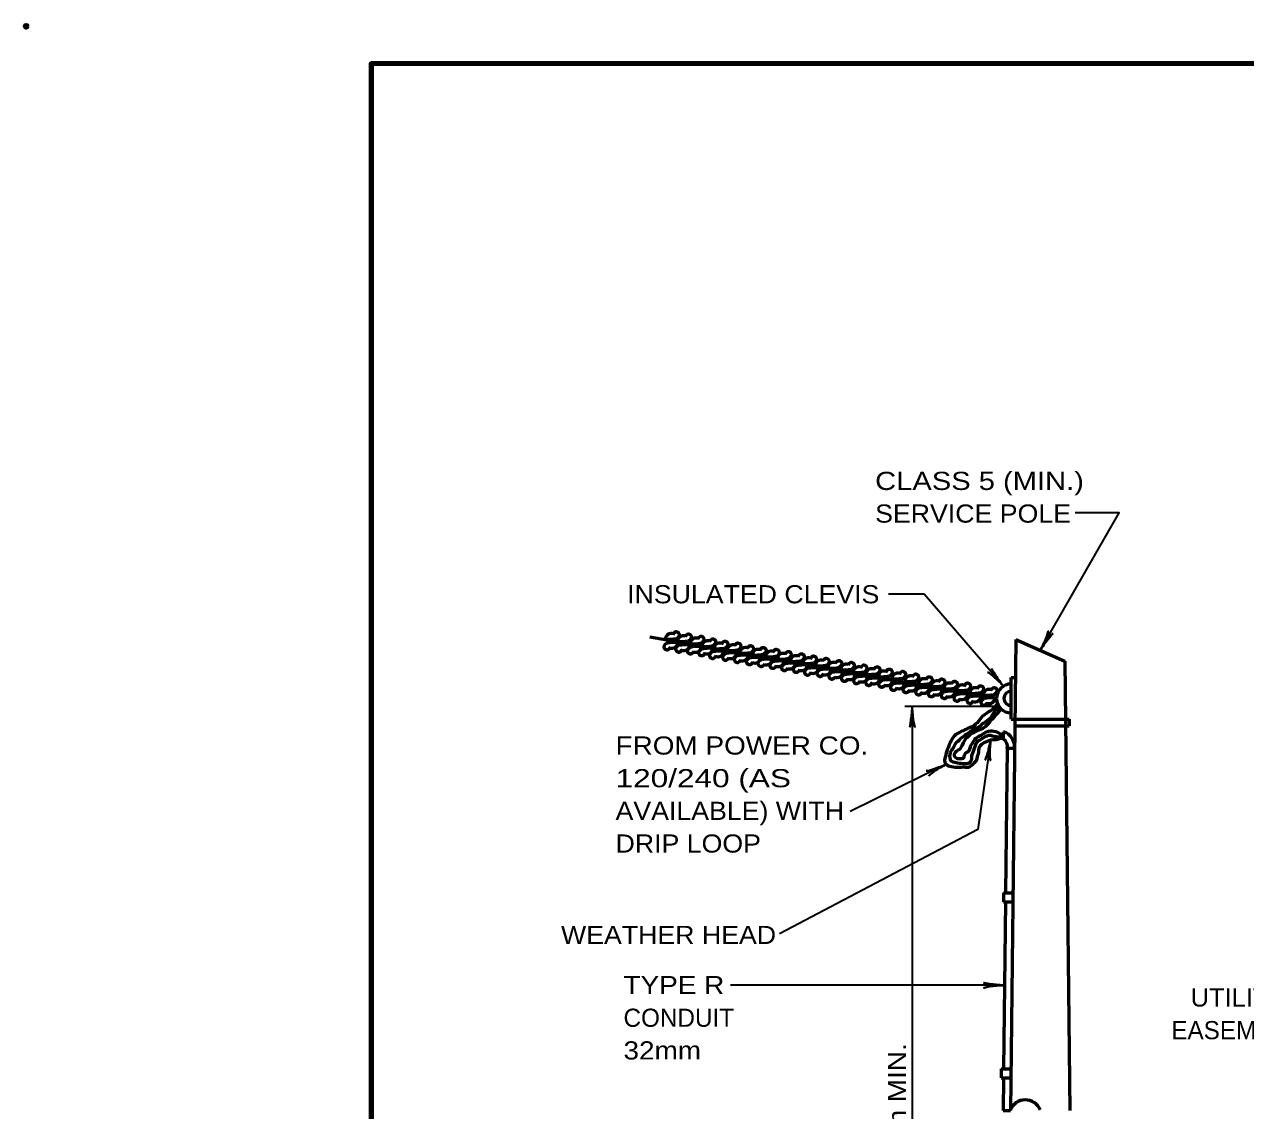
# Model space of a CAD drawing. Extents: x -111 to 744, y -77 to 467.
# Drawn here: x -111.3 to 90.6, y 287.1 to 466.7 of the extents above; entities that cross this region are included whole.
import ezdxf
from ezdxf.enums import TextEntityAlignment as Align

# ---------------------------------------------------------------- set-up
doc = ezdxf.new("R2010")
doc.units = 0
doc.header["$LTSCALE"] = 1.2
doc.header["$PDMODE"] = 32
doc.header["$PDSIZE"] = 0.6
doc.layers.add('1', color=7, linetype='Continuous', lineweight=53)

msp = doc.modelspace()

# ---------------------------------------------------------------- linework, layer by layer
at = {"layer": '1', "lineweight": 35}
for p, q in [((37.467, 372.463), (31.541, 372.476)), ((50.549, 357.271), (37.467, 372.463)), ((49.884, 353.927), (34.284, 353.927)), ((41.118, 344.372), (25.249, 336.554)), ((50.739, 307.831), (5.456, 307.865))]:
    msp.add_line(p, q, dxfattribs=at)
at = {"layer": '1'}
for p, q in [((49.439, 355.247), (-7.877, 365.353)), ((52.589, 364.996), (51.704, 287.117)), ((52.589, 364.996), (60.705, 361.396)), ((60.705, 361.396), (61.549, 287.117)), ((51.839, 358.697), (52.517, 358.697)), ((51.839, 351.797), (51.839, 358.697)), ((51.839, 351.797), (61.427, 351.797)), ((61.427, 351.797), (61.427, 350.717)), ((50.585, 348.511), (50.585, 349.711)), ((52.427, 350.717), (61.427, 350.717)), ((51.185, 347.011), (50.913, 323.131)), ((51.185, 347.011), (52.385, 347.011)), ((50.596, 323.131), (52.096, 323.131)), ((50.596, 323.131), (50.596, 321.631)), ((50.896, 321.631), (50.583, 294.031)), ((50.596, 321.631), (52.096, 321.631)), ((50.204, 294.031), (51.704, 294.031)), ((50.204, 294.031), (50.204, 292.531)), ((50.204, 292.531), (51.704, 292.531)), ((50.565, 292.531), (50.504, 287.131)), ((50.504, 287.131), (51.704, 287.131))]:
    msp.add_line(p, q, dxfattribs=at)
at = {"layer": '1', "lineweight": 158}
msp.add_lwpolyline([(737.728, 460.265), (-53.972, 460.165), (-53.872, -65.835)], dxfattribs=at)
at = {"layer": '1', "lineweight": 35}
for points in [[(56.647, 363.196), (69.692, 385.907), (62.415, 385.907)], [(35.483, 353.927), (35.483, 211.531), (35.483, 139.517)], [(48.457, 348.411), (46.345, 333.592), (13.529, 316.314)]]:
    msp.add_lwpolyline(points, dxfattribs=at)
at = {"layer": '1'}
for points in [[(49.666, 354.362), (49.472, 354.169), (49.327, 354.024), (49.158, 353.83), (48.965, 353.636), (48.82, 353.491), (48.578, 353.322), (48.384, 353.128), (48.118, 353.007), (47.804, 352.79), (47.465, 352.596), (47.272, 352.403), (47.054, 352.233), (46.812, 351.992), (46.692, 351.822), (46.474, 351.532), (46.232, 351.217), (45.966, 350.976), (45.724, 350.782), (45.434, 350.613), (45.241, 350.516), (45.023, 350.443), (44.805, 350.347), (44.612, 350.25), (44.394, 350.129), (44.177, 350.032), (43.935, 349.911), (43.669, 349.814), (43.427, 349.694), (43.185, 349.572), (42.968, 349.452), (42.677, 349.258), (42.436, 349.016), (42.194, 348.75), (42.024, 348.484), (41.855, 348.194), (41.734, 347.904), (41.613, 347.637), (41.541, 347.396), (41.444, 347.105), (41.275, 346.791), (41.178, 346.549), (41.105, 346.259), (41.033, 345.944), (40.96, 345.654), (40.888, 345.339), (40.84, 345.049), (40.864, 344.662), (40.985, 344.493), (41.251, 344.251), (41.444, 344.13), (41.71, 344.057), (41.952, 343.985), (42.315, 343.936), (42.556, 343.912), (42.871, 343.888), (43.137, 343.888), (43.403, 343.912), (43.645, 343.912), (43.911, 343.936), (44.225, 343.888), (44.588, 343.864), (44.805, 343.888), (45.071, 344.009), (45.337, 344.202), (45.555, 344.372), (45.724, 344.59), (45.942, 344.807), (46.111, 345.001), (46.208, 345.291), (46.28, 345.581), (46.353, 345.872), (46.45, 346.089), (46.498, 346.404), (46.522, 346.718), (46.546, 347.033), (46.643, 347.274), (46.788, 347.492), (47.006, 347.686), (47.199, 347.879), (47.417, 347.976), (47.635, 348.073), (47.925, 348.17), (48.215, 348.315), (48.457, 348.411), (48.844, 348.484), (49.086, 348.46), (49.352, 348.484), (49.642, 348.532), (49.932, 348.605), (50.174, 348.653), (50.44, 348.678), (50.536, 348.702)], [(49.884, 353.927), (49.448, 353.516), (49.279, 353.346), (49.013, 352.959), (48.82, 352.669), (48.674, 352.475), (48.529, 352.113), (48.312, 351.919), (48.07, 351.75), (47.828, 351.556), (47.562, 351.338), (47.296, 351.169), (47.03, 351.024), (46.812, 350.758), (46.619, 350.613), (46.208, 350.395), (45.869, 350.274), (45.628, 350.153), (45.434, 350.008), (45.216, 349.887), (44.999, 349.742), (44.757, 349.524), (44.588, 349.403), (44.37, 349.258), (44.152, 349.089), (43.79, 348.871), (43.62, 348.75), (43.475, 348.605), (43.258, 348.363), (43.04, 348.145), (42.822, 348), (42.653, 347.807), (42.532, 347.589), (42.411, 347.347), (42.315, 347.129), (42.169, 346.887), (42, 346.718), (41.855, 346.476), (41.783, 346.234), (41.71, 345.993), (41.662, 345.726), (41.686, 345.46), (41.758, 345.17), (41.879, 344.928), (42.194, 344.759), (42.532, 344.686), (42.968, 344.614), (43.282, 344.565), (43.524, 344.541), (43.886, 344.517), (44.128, 344.517), (44.418, 344.517), (44.709, 344.541), (44.95, 344.59), (45.12, 344.759), (45.192, 344.952), (45.313, 345.218), (45.337, 345.509), (45.361, 345.726), (45.41, 345.968), (45.482, 346.234), (45.603, 346.525), (45.748, 346.839), (45.845, 347.178), (45.942, 347.492), (46.039, 347.783), (46.184, 348.024), (46.377, 348.218), (46.595, 348.363), (46.861, 348.532), (47.151, 348.702), (47.393, 348.847), (47.659, 348.992), (47.876, 349.065), (48.167, 349.161), (48.408, 349.161), (48.723, 349.089), (49.037, 349.016), (49.4, 348.968), (49.666, 348.919), (49.932, 348.944), (50.198, 348.992), (50.416, 349.065), (50.609, 349.113)], [(50.198, 353.491), (49.932, 353.177), (49.472, 352.717), (49.255, 352.5), (49.086, 352.282), (48.771, 351.871), (48.626, 351.725), (48.481, 351.58), (48.239, 351.314), (47.973, 350.976), (47.804, 350.806), (47.61, 350.589), (47.393, 350.419), (47.151, 350.274), (46.764, 350.105), (46.522, 350.008), (46.305, 349.911), (46.111, 349.814), (45.845, 349.694), (45.482, 349.5), (45.144, 349.307), (44.975, 349.161), (44.781, 348.992), (44.539, 348.798), (44.273, 348.581), (44.104, 348.266), (43.911, 347.928), (43.693, 347.396), (43.572, 347.226), (43.354, 346.887), (43.04, 346.67), (42.726, 346.452), (42.556, 346.283), (42.411, 346.017), (42.436, 345.775), (42.605, 345.557), (42.895, 345.339), (43.233, 345.291), (43.451, 345.291), (43.717, 345.291), (43.935, 345.388), (44.056, 345.63), (44.152, 345.847), (44.249, 346.065), (44.37, 346.234), (44.588, 346.38), (44.878, 346.621), (45.023, 346.936), (45.12, 347.226), (45.192, 347.468), (45.337, 347.686), (45.458, 347.879), (45.579, 348.073), (45.7, 348.291), (45.845, 348.532), (46.014, 348.702), (46.256, 348.871), (46.498, 349.016), (46.861, 349.161), (47.127, 349.331), (47.32, 349.476), (47.538, 349.621), (47.731, 349.742), (48.094, 349.863), (48.408, 349.911), (48.699, 349.887), (48.965, 349.863), (49.327, 349.766), (49.545, 349.669), (49.763, 349.548), (50.004, 349.403), (50.198, 349.307), (50.488, 349.185), (50.585, 349.161)]]:
    msp.add_lwpolyline(points, dxfattribs=at)
for centre, radius, start, end in [((51.839, 355.247), 2.4, 90, 270), ((51.839, 355.247), 1.2, 90, 270), ((49.865, 347.281), 2.534, 353.86968, 73.51046), ((49.936, 347.381), 1.302, 343.45685, 60.14597), ((54.165, 286.251), 2.644, 21.451, 158.54901)]:
    msp.add_arc(centre, radius, start, end, dxfattribs=at)
at = {"layer": '1', "lineweight": 40}
for centre, major_axis, ratio, start_param, end_param in [((57.012, 364.497), (-0.905, -1.951), 0.122415, 0.8963533, 3.1415927), ((57.012, 364.497), (-0.905, -1.951), 0.122415, 0.8963533, 3.1415927), ((57.537, 364.236), (1.233, 1.723), 0.07063, 6.2823074, 8.5597026), ((57.537, 364.236), (1.233, 1.723), 0.07063, 6.2823074, 8.5597026), ((49.444, 358.047), (1.54, -1.502), 0.122415, 0.8963533, 3.1415927), ((49.444, 358.047), (1.54, -1.502), 0.122415, 0.8963533, 3.1415927), ((49.864, 358.455), (1.216, -1.735), 0.07063, 3.1407148, 5.41811), ((49.864, 358.455), (1.216, -1.735), 0.07063, 3.1407148, 5.41811), ((35.23, 352.582), (0.211, 2.108), 0.07063, 3.1407148, 5.41811), ((35.23, 352.582), (0.211, 2.108), 0.07063, 3.1407148, 5.41811), ((35.23, 352.582), (0.211, 2.108), 0.07063, 3.1407148, 5.41811), ((35.815, 352.617), (-0.187, 2.143), 0.122415, 0.8963533, 3.1415927), ((35.815, 352.617), (-0.187, 2.143), 0.122415, 0.8963533, 3.1415927), ((35.815, 352.617), (-0.187, 2.143), 0.122415, 0.8963533, 3.1415927), ((48.016, 347.116), (-0.506, -2.057), 0.07063, 6.2823074, 8.5597026), ((48.016, 347.116), (-0.506, -2.057), 0.07063, 6.2823074, 8.5597026), ((48.6, 347.068), (0.117, 2.148), 0.122415, 0.8963533, 3.1415927), ((48.6, 347.068), (0.117, 2.148), 0.122415, 0.8963533, 3.1415927), ((39.799, 344.005), (-1.984, -0.742), 0.07063, 6.2823074, 8.5597026), ((39.799, 344.005), (-1.984, -0.742), 0.07063, 6.2823074, 8.5597026), ((40.09, 343.496), (1.839, 1.115), 0.122415, 0.8963533, 3.1415927), ((40.09, 343.496), (1.839, 1.115), 0.122415, 0.8963533, 3.1415927), ((49.43, 307.5), (2.143, 0.186), 0.122415, 0.8963533, 3.1415927), ((49.395, 308.085), (-2.108, 0.212), 0.07063, 6.2823074, 8.5597026)]:
    msp.add_ellipse(centre, major_axis=major_axis, ratio=ratio, start_param=start_param, end_param=end_param, dxfattribs=at)
at = {"layer": '1'}
for points in [[(-4.053, 365.839), (-3.532, 366.286), (-3.086, 365.988), (-3.383, 365.169), (-3.979, 365.02), (-5.244, 365.169), (-4.797, 365.913), (-4.053, 365.988)], [(-2.044, 365.467), (-1.523, 365.913), (-1.076, 365.616), (-1.374, 364.797), (-1.969, 364.648), (-3.234, 364.797), (-2.788, 365.541), (-2.044, 365.616)], [(0.04, 365.095), (0.561, 365.541), (1.007, 365.243), (0.71, 364.425), (0.114, 364.276), (-1.151, 364.425), (-0.704, 365.169), (0.04, 365.243)], [(-4.499, 363.68), (-5.02, 363.233), (-5.467, 363.531), (-5.169, 364.35), (-4.574, 364.499), (-3.309, 364.35), (-3.755, 363.606), (-4.499, 363.531)], [(-2.564, 363.308), (-3.085, 362.861), (-3.532, 363.159), (-3.234, 363.978), (-2.639, 364.127), (-1.374, 363.978), (-1.82, 363.233), (-2.564, 363.159)], [(-0.63, 363.01), (-1.151, 362.564), (-1.597, 362.861), (-1.299, 363.68), (-0.704, 363.829), (0.561, 363.68), (0.115, 362.936), (-0.63, 362.861)], [(1.231, 362.712), (0.71, 362.266), (0.264, 362.564), (0.561, 363.382), (1.157, 363.531), (2.421, 363.382), (1.975, 362.638), (1.231, 362.564)], [(1.975, 364.648), (2.496, 365.095), (2.942, 364.797), (2.645, 363.978), (2.049, 363.829), (0.784, 363.978), (1.231, 364.722), (1.975, 364.797)], [(3.984, 364.276), (4.505, 364.722), (4.952, 364.425), (4.654, 363.606), (4.059, 363.457), (2.794, 363.606), (3.24, 364.35), (3.984, 364.425)], [(6.142, 363.978), (6.663, 364.425), (7.11, 364.127), (6.812, 363.308), (6.217, 363.159), (4.952, 363.308), (5.398, 364.052), (6.142, 364.127)], [(8.226, 363.531), (8.747, 363.978), (9.193, 363.68), (8.896, 362.861), (8.3, 362.712), (7.035, 362.861), (7.482, 363.606), (8.226, 363.68)], [(10.309, 363.233), (10.83, 363.68), (11.277, 363.382), (10.979, 362.564), (10.384, 362.415), (9.119, 362.564), (9.565, 363.308), (10.309, 363.382)], [(12.468, 362.936), (12.989, 363.382), (13.435, 363.085), (13.137, 362.266), (12.542, 362.117), (11.277, 362.266), (11.724, 363.01), (12.468, 363.085)], [(3.017, 362.266), (2.496, 361.819), (2.05, 362.117), (2.347, 362.936), (2.943, 363.085), (4.208, 362.936), (3.761, 362.191), (3.017, 362.117)], [(5.175, 361.968), (4.654, 361.521), (4.208, 361.819), (4.505, 362.638), (5.101, 362.787), (6.365, 362.638), (5.919, 361.894), (5.175, 361.819)], [(7.11, 361.596), (6.589, 361.149), (6.142, 361.447), (6.44, 362.266), (7.035, 362.415), (8.3, 362.266), (7.854, 361.521), (7.11, 361.447)], [(9.119, 361.224), (8.598, 360.777), (8.152, 361.075), (8.449, 361.894), (9.045, 362.042), (10.31, 361.894), (9.863, 361.149), (9.119, 361.075)], [(11.054, 360.926), (10.533, 360.479), (10.086, 360.777), (10.384, 361.596), (10.979, 361.745), (12.244, 361.596), (11.798, 360.851), (11.054, 360.777)], [(12.989, 360.628), (12.468, 360.181), (12.021, 360.479), (12.319, 361.298), (12.914, 361.447), (14.179, 361.298), (13.733, 360.554), (12.989, 360.479)], [(14.477, 362.564), (14.998, 363.01), (15.444, 362.712), (15.147, 361.894), (14.551, 361.745), (13.286, 361.894), (13.733, 362.638), (14.477, 362.712)], [(16.635, 362.191), (17.156, 362.638), (17.602, 362.34), (17.305, 361.521), (16.709, 361.372), (15.444, 361.521), (15.891, 362.266), (16.635, 362.34)], [(18.644, 361.819), (19.165, 362.266), (19.611, 361.968), (19.314, 361.149), (18.719, 361), (17.454, 361.149), (17.9, 361.894), (18.644, 361.968)], [(20.728, 361.447), (21.249, 361.894), (21.695, 361.596), (21.398, 360.777), (20.802, 360.628), (19.537, 360.777), (19.984, 361.521), (20.728, 361.596)], [(22.812, 361.075), (23.332, 361.521), (23.779, 361.224), (23.481, 360.405), (22.886, 360.256), (21.621, 360.405), (22.067, 361.149), (22.812, 361.224)], [(14.924, 360.256), (14.403, 359.809), (13.956, 360.107), (14.254, 360.926), (14.849, 361.075), (16.114, 360.926), (15.668, 360.181), (14.924, 360.107)], [(16.858, 359.958), (16.337, 359.512), (15.891, 359.809), (16.189, 360.628), (16.784, 360.777), (18.049, 360.628), (17.602, 359.884), (16.858, 359.809)], [(18.719, 359.511), (18.198, 359.065), (17.751, 359.363), (18.049, 360.181), (18.644, 360.33), (19.909, 360.181), (19.463, 359.437), (18.719, 359.363)], [(20.802, 359.288), (20.282, 358.841), (19.835, 359.139), (20.133, 359.958), (20.728, 360.107), (21.993, 359.958), (21.547, 359.214), (20.802, 359.139)], [(22.737, 358.841), (22.216, 358.395), (21.77, 358.692), (22.067, 359.511), (22.663, 359.66), (23.928, 359.511), (23.481, 358.767), (22.737, 358.692)], [(24.895, 360.777), (25.416, 361.224), (25.863, 360.926), (25.565, 360.107), (24.97, 359.958), (23.704, 360.107), (24.151, 360.851), (24.895, 360.926)], [(24.821, 358.469), (24.3, 358.023), (23.854, 358.32), (24.151, 359.139), (24.747, 359.288), (26.012, 359.139), (25.565, 358.395), (24.821, 358.32)], [(26.979, 360.33), (27.5, 360.777), (27.946, 360.479), (27.649, 359.66), (27.053, 359.511), (25.788, 359.66), (26.235, 360.405), (26.979, 360.479)], [(29.137, 360.033), (29.658, 360.479), (30.104, 360.181), (29.807, 359.363), (29.211, 359.214), (27.946, 359.363), (28.393, 360.107), (29.137, 360.181)], [(31.146, 359.66), (31.667, 360.107), (32.114, 359.809), (31.816, 358.99), (31.221, 358.841), (29.956, 358.99), (30.402, 359.735), (31.146, 359.809)], [(33.379, 359.288), (33.9, 359.735), (34.346, 359.437), (34.048, 358.618), (33.453, 358.469), (32.188, 358.618), (32.635, 359.363), (33.379, 359.437)], [(26.83, 358.097), (26.309, 357.65), (25.863, 357.948), (26.16, 358.767), (26.756, 358.916), (28.021, 358.767), (27.574, 358.023), (26.83, 357.948)], [(28.839, 357.799), (28.319, 357.353), (27.872, 357.65), (28.17, 358.469), (28.765, 358.618), (30.03, 358.469), (29.584, 357.725), (28.839, 357.65)], [(30.998, 357.502), (30.477, 357.055), (30.03, 357.353), (30.328, 358.172), (30.923, 358.32), (32.188, 358.172), (31.742, 357.427), (30.998, 357.353)], [(32.932, 356.98), (32.411, 356.534), (31.965, 356.832), (32.263, 357.65), (32.858, 357.799), (34.123, 357.65), (33.676, 356.906), (32.932, 356.832)], [(35.016, 356.608), (34.495, 356.162), (34.049, 356.459), (34.346, 357.278), (34.942, 357.427), (36.207, 357.278), (35.76, 356.534), (35.016, 356.459)], [(35.537, 358.841), (36.058, 359.288), (36.504, 358.99), (36.206, 358.172), (35.611, 358.023), (34.346, 358.172), (34.793, 358.916), (35.537, 358.99)], [(37.769, 358.395), (38.29, 358.841), (38.737, 358.544), (38.439, 357.725), (37.844, 357.576), (36.579, 357.725), (37.025, 358.469), (37.769, 358.544)], [(39.853, 358.023), (40.374, 358.469), (40.82, 358.172), (40.523, 357.353), (39.927, 357.204), (38.662, 357.353), (39.109, 358.097), (39.853, 358.172)], [(41.937, 357.65), (42.457, 358.097), (42.904, 357.799), (42.606, 356.98), (42.011, 356.832), (40.746, 356.98), (41.192, 357.725), (41.937, 357.799)], [(44.095, 357.353), (44.616, 357.799), (45.062, 357.502), (44.764, 356.683), (44.169, 356.534), (42.904, 356.683), (43.351, 357.427), (44.095, 357.502)], [(46.253, 356.906), (46.774, 357.353), (47.22, 357.055), (46.922, 356.236), (46.327, 356.087), (45.062, 356.236), (45.509, 356.98), (46.253, 357.055)], [(37.1, 356.236), (36.579, 355.789), (36.132, 356.087), (36.43, 356.906), (37.025, 357.055), (38.29, 356.906), (37.844, 356.162), (37.1, 356.087)], [(39.183, 355.938), (38.662, 355.492), (38.216, 355.789), (38.514, 356.608), (39.109, 356.757), (40.374, 356.608), (39.927, 355.864), (39.183, 355.789)], [(41.341, 355.641), (40.821, 355.194), (40.374, 355.492), (40.672, 356.31), (41.267, 356.459), (42.532, 356.31), (42.086, 355.566), (41.341, 355.492)], [(43.425, 355.194), (42.904, 354.747), (42.458, 355.045), (42.755, 355.864), (43.351, 356.013), (44.616, 355.864), (44.169, 355.119), (43.425, 355.045)], [(45.583, 354.822), (45.062, 354.375), (44.616, 354.673), (44.913, 355.492), (45.509, 355.641), (46.774, 355.492), (46.327, 354.747), (45.583, 354.673)], [(47.89, 354.524), (47.369, 354.077), (46.923, 354.375), (47.22, 355.194), (47.816, 355.343), (49.081, 355.194), (48.634, 354.45), (47.89, 354.375)], [(48.485, 356.608), (49.006, 357.055), (49.453, 356.757), (49.155, 355.938), (48.56, 355.789), (47.295, 355.938), (47.741, 356.683), (48.485, 356.757)]]:
    msp.add_spline(points, degree=3, dxfattribs=at)
msp.add_point((-110.972, 466.365), dxfattribs=at)

# ---------------------------------------------------------------- texts
for s, width, p in [('CLASS 5 (MIN.)', 1.2, (29.354, 389.707)), ('SERVICE POLE', 1.1, (29.354, 384.307)), ('INSULATED CLEVIS', 1.1, (-11.642, 370.972)), ('FROM POWER CO.', 1.15, (-13.555, 345.964)), ('120/240 (AS', 1.3, (-13.555, 340.564)), ('AVAILABLE) WITH', 1.1, (-13.555, 335.164)), ('DRIP LOOP', 1.1, (-13.555, 329.764)), ('WEATHER HEAD', 1.1, (-22.574, 314.653)), ('TYPE R', 1.15, (-12.24, 306.363)), ('32mm', 1.15, (-12.24, 295.563))]:
    msp.add_text(s, height=3, dxfattribs=dict(at, width=width)).set_placement(p)
at = {"layer": '1', "width": 1.05}
msp.add_text('UTILITY', height=3, dxfattribs=at).set_placement((89.343, 304.312), align=Align.CENTER)
at = {"layer": '1'}
msp.add_text('CONDUIT', height=3, dxfattribs=at).set_placement((-12.24, 300.963))
msp.add_text('EASEMENT', height=3, dxfattribs=at).set_placement((89.343, 298.912), align=Align.CENTER)
at = {"layer": '1', "width": 1.15}
msp.add_text('6.1m MIN.', height=3, rotation=90, dxfattribs=at).set_placement((34.481, 287.613), align=Align.CENTER)

doc.saveas('drawing.dxf')
